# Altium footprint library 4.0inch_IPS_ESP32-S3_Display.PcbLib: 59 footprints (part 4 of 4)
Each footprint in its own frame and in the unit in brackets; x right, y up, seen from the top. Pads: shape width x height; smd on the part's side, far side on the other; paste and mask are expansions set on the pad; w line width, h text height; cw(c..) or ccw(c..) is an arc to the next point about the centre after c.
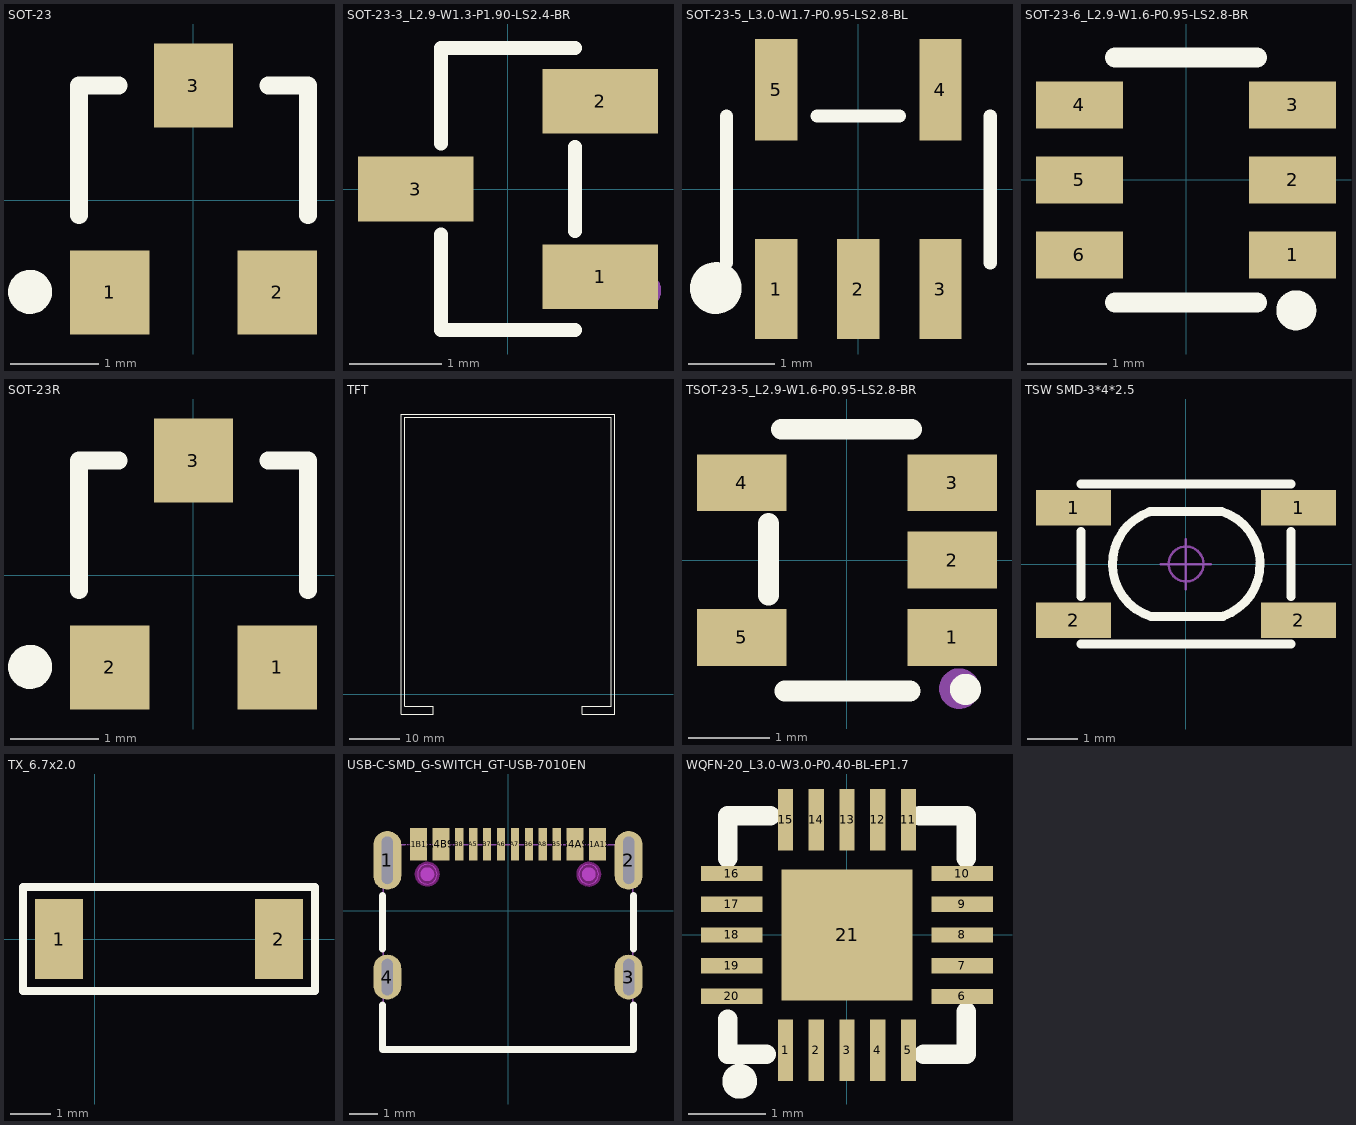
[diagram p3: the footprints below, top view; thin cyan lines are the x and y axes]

## SOT-23 [mm]
pads (3):
  rect 0.9x0.95 smd: 1(-0.95,-1.048) 2(0.95,-1.048) 3(0,1.302)
Top Overlay:
  circle w0.25: c-1.856,-1.041 r0.125
  lines w0.2: -1.3,-0.173 -1.3,1.302 -0.85,1.302 ; 0.85,1.302 1.3,1.302 1.3,-0.173
3D body "SOT-23-3.STEP": height 1.2, standoff 0, extent -1.448,-1.327 1.452,1.473

## SOT-23-3_L2.9-W1.3-P1.90-LS2.4-BR [mm]
pads (3):
  rect 1.25x0.7 smd: 1(1,-0.95) 2(1,0.95) 3(-1,0)
Top Overlay:
  lines w0.152: -0.726,-0.495 -0.726,-1.526 0.726,-1.526 ; -0.726,0.495 -0.726,1.526 0.726,1.526 ; 0.726,-0.455 0.726,0.455
Mechanical 15:
  circle w0.2: c1.46,-1.1 r0.1
3D body "bss138.stp": height 1.1, standoff 0, extent -1.1,-1.491 1.3,1.409

## SOT-23-5_L3.0-W1.7-P0.95-LS2.8-BL [mm]
pads (5):
  rect 0.49x1.157 smd: 1(-0.95,-1.154) 2(0,-1.154) 3(0.95,-1.154)
  rect 0.49x1.175 smd: 4(0.95,1.154) 5(-0.95,1.154)
Top Overlay:
  circle w0.3: c-1.651,-1.143 r0.15
  lines w0.152: -1.526,-0.851 -1.526,0.851 ; -0.476,0.851 0.476,0.851 ; 1.526,-0.851 1.526,0.851
3D body "CircuitWorks-SOT-23-5.STEP": height 1.1, standoff 0, extent -1.476,-1.366 1.524,1.134

## SOT-23-6_L2.9-W1.6-P0.95-LS2.8-BR [mm]
pads (6):
  rect 1.1x0.6 smd paste+0 mask+0.051: 1(1.35,-0.95) 2(1.35,0) 3(1.35,0.95) 4(-1.35,0.95) 5(-1.35,0) 6(-1.35,-0.95)
Top Overlay:
  circle w0.254: c1.397,-1.651 r0.127
  lines w0.254: -0.9,-1.55 0.9,-1.55 ; -0.9,1.55 0.9,1.55
Mechanical 6:
  circle w0.2: c1.4,-0.95 r0.1

## SOT-23R [mm]
pads (3):
  rect 0.9x0.95 smd: 1(0.95,-1.048) 2(-0.95,-1.048) 3(0,1.302)
Top Overlay:
  circle w0.25: c-1.856,-1.041 r0.125
  lines w0.2: -1.3,-0.173 -1.3,1.302 -0.85,1.302 ; 0.85,1.302 1.3,1.302 1.3,-0.173
3D body "1364886p.stp": height 1, standoff 0, extent -1.45,-0.998 1.45,1.302

## TFT [mm]
Top Overlay:
  lines w0.1: 133.223,-3.937 133.223,56.063 175.823,56.063 175.823,-3.937 169.418,-3.937 169.418,-2.413 175.133,-2.413 175.133,55.372 133.858,55.372 133.858,-2.413 139.558,-2.413 139.558,-3.937 133.223,-3.937
3D body: height 0.1, standoff 0, extent 133.153,-2.413 175.753,55.315
3D body: height 2.3, standoff 0.1, extent 133.223,-3.937 175.823,56.063
3D body: height 3.3, standoff 2.3, extent 133.731,-2.286 175.133,55.63

## TSOT-23-5_L2.9-W1.6-P0.95-LS2.8-BR [mm]
pads (5):
  rect 1.1x0.7 smd: 1(1.294,-0.951) 2(1.294,-0.001) 3(1.294,0.951) 4(-1.294,0.951) 5(-1.294,-0.949)
Top Overlay:
  circle w0.254: c1.456,-1.589 r0.064
  lines w0.254: -0.966,-0.433 -0.966,0.451 ; -0.806,1.609 0.794,1.609 ; -0.766,-1.609 0.774,-1.609
Mechanical 6:
  circle w0.25: c1.38,-1.58 r0.125
3D body "User Library-TSSOP-5 (SOT-23-5 PITCH 0_65).STEP": height 1.15, standoff 0.04, extent -1.252,-1.125 0.998,1.125

## TSW SMD-3*4*2.5 [mm] "3*4*2.5mm"
height 2.5
pads (4):
  rect 1.5x0.7 smd: 1(-2.25,1.125) 1(2.25,1.125) 2(-2.25,-1.125) 2(2.25,-1.125)
Top Overlay:
  lines w0.178: -2.1,-1.6 2.1,-1.6 ; -2.1,-0.65 -2.1,0.65 ; -2.1,1.6 2.1,1.6 ; -0.738,1.037 ccw(c-0.372,0) -0.7,-1.05 0.737,-1.05 ; -0.725,1.05 0.712,1.05 cw(c0.384,0) 0.75,-1.037 ; 2.1,-0.65 2.1,0.65
Mechanical 15:
  circle w0.05: c0,0 r0.35
  lines w0.05: -0.5,0 0.5,0 ; 0,-0.5 0,0.5
3D body "key.STEP": height 2.5, standoff 0, extent -2.6,-1.65 2.6,1.6

## TX_6.7x2.0 [mm]
pads (2):
  rect 1.2x2 smd: 1(-0.889,0) 2(4.611,0)
Top Overlay:
  lines w0.2: -1.789,-1.3 5.511,-1.3 5.511,1.3 -1.789,1.3 -1.789,-1.3

## USB-C-SMD_G-SWITCH_GT-USB-7010EN [mm]
pads (16):
  oval 1x2.1 hole 0.4 slot 1.7 at 90 deg mask+0.05: 1(-4.32,1.802) 2(4.32,1.802)
  oval 1x1.6 hole 0.4 slot 1.3 at 90 deg mask+0.05: 3(4.32,-2.378) 4(-4.32,-2.378)
  rect 0.6x1.15 smd mask+0.05: A1B12(-3.2,2.378) A4B9(-2.4,2.378) B1A12(3.2,2.378) B4A9(2.4,2.378)
  rect 0.3x1.15 smd mask+0.05: A5(-1.25,2.378) A6(-0.25,2.378) A7(0.25,2.378) A8(1.25,2.378) B5(1.75,2.378) B6(0.75,2.378) B7(-0.75,2.378) B8(-1.75,2.378)
Top Overlay:
  lines w0.254: -4.5,-3.386 -4.5,-4.978 4.5,-4.978 4.5,-3.386 ; -4.5,-1.369 -4.5,0.544 ; 4.5,-1.369 4.5,0.544
Top Paste:
  region: 3.82,2.352 3.82,2.452 3.896,2.636 4.037,2.776 4.221,2.852 4.42,2.852 4.603,2.776 4.744,2.636 4.82,2.452 4.82,2.352 4.82,1.252 4.82,1.153 4.744,0.969 4.603,0.829 4.42,0.752 4.221,0.752 4.037,0.829 3.896,0.969 3.82,1.153 3.82,1.252
  region: 3.82,-2.078 3.82,-1.978 3.896,-1.794 4.037,-1.654 4.221,-1.578 4.42,-1.578 4.603,-1.654 4.744,-1.794 4.82,-1.978 4.82,-2.078 4.82,-2.678 4.82,-2.777 4.744,-2.961 4.603,-3.101 4.42,-3.178 4.221,-3.178 4.037,-3.101 3.896,-2.961 3.82,-2.777 3.82,-2.678
  region: -4.82,-2.078 -4.82,-1.978 -4.744,-1.794 -4.603,-1.654 -4.419,-1.578 -4.221,-1.578 -4.037,-1.654 -3.896,-1.794 -3.82,-1.978 -3.82,-2.078 -3.82,-2.678 -3.82,-2.777 -3.896,-2.961 -4.037,-3.101 -4.221,-3.178 -4.419,-3.178 -4.603,-3.101 -4.744,-2.961 -4.82,-2.777 -4.82,-2.678
  region: -4.82,2.352 -4.82,2.452 -4.744,2.636 -4.603,2.776 -4.419,2.852 -4.221,2.852 -4.037,2.776 -3.896,2.636 -3.82,2.452 -3.82,2.352 -3.82,1.252 -3.82,1.153 -3.896,0.969 -4.037,0.829 -4.221,0.752 -4.419,0.752 -4.603,0.829 -4.744,0.969 -4.82,1.153 -4.82,1.252
  region: -3.5,2.952 -2.9,2.952 -2.9,1.802 -3.5,1.802
  region: -2.7,2.952 -2.1,2.952 -2.1,1.802 -2.7,1.802
  region: -1.9,2.952 -1.6,2.952 -1.6,1.802 -1.9,1.802
  region: -1.4,2.952 -1.1,2.952 -1.1,1.802 -1.4,1.802
  region: -0.9,2.952 -0.6,2.952 -0.6,1.802 -0.9,1.802
  region: -0.4,2.952 -0.1,2.952 -0.1,1.802 -0.4,1.802
  region: 0.1,2.952 0.4,2.952 0.4,1.802 0.1,1.802
  region: 0.6,2.952 0.9,2.952 0.9,1.802 0.6,1.802
  region: 1.1,2.952 1.4,2.952 1.4,1.802 1.1,1.802
  region: 1.6,2.952 1.9,2.952 1.9,1.802 1.6,1.802
  region: 2.1,2.952 2.7,2.952 2.7,1.802 2.1,1.802
  region: 2.9,2.952 3.5,2.952 3.5,1.802 2.9,1.802
Keep-Out Layer:
  board cut-out: -2.54,1.302 -2.54,1.372 -2.593,1.501 -2.692,1.599 -2.82,1.652 -2.96,1.652 -3.088,1.599 -3.187,1.501 -3.24,1.372 -3.24,1.302 -3.24,1.233 -3.187,1.104 -3.088,1.006 -2.96,0.952 -2.82,0.952 -2.692,1.006 -2.593,1.104 -2.54,1.233
  board cut-out: 3.24,1.302 3.24,1.372 3.187,1.5 3.088,1.599 2.96,1.652 2.82,1.652 2.692,1.599 2.593,1.5 2.54,1.372 2.54,1.302 2.54,1.232 2.593,1.104 2.692,1.005 2.82,0.952 2.96,0.952 3.088,1.005 3.187,1.104 3.24,1.232
Keep-Out Layer:
  circle w0.1: c2.893,1.305 r0.4
  circle w0.1: c-2.89,1.307 r0.4
Mechanical 1:
  circle w0.005: c-2.89,1.302 r0.35
  circle w0.005: c2.89,1.302 r0.35
Mechanical 6:
  circle w0.25: c2.89,1.302 r0.125
  circle w0.25: c-2.89,1.302 r0.125
Mechanical 15:
  region: -4.41,2.597 -4.41,2.622 -4.445,2.657 -4.495,2.657 -4.53,2.622 -4.53,2.597 -4.53,2.572 -4.495,2.537 -4.445,2.537 -4.41,2.572
  region: 4.17,-1.978 4.47,-1.978 4.47,-2.778 4.17,-2.778
  region: -4.47,-1.978 -4.17,-1.978 -4.17,-2.778 -4.47,-2.778
  region: -4.47,2.352 -4.17,2.352 -4.17,1.252 -4.47,1.252
  region: 4.17,2.352 4.47,2.352 4.47,1.252 4.17,1.252
  region: 1.65,2.597 1.85,2.597 1.85,1.847 1.65,1.847
  region: 1.15,2.597 1.35,2.597 1.35,1.847 1.15,1.847
  region: 0.65,2.597 0.85,2.597 0.85,1.847 0.65,1.847
  region: 0.15,2.597 0.35,2.597 0.35,1.847 0.15,1.847
  region: -0.35,2.597 -0.15,2.597 -0.15,1.847 -0.35,1.847
  region: -0.85,2.597 -0.65,2.597 -0.65,1.847 -0.85,1.847
  region: -1.35,2.597 -1.15,2.597 -1.15,1.847 -1.35,1.847
  region: -1.85,2.597 -1.65,2.597 -1.65,1.847 -1.85,1.847
  region: 3,2.597 3.4,2.597 3.4,1.847 3,1.847
  region: 2.2,2.597 2.6,2.597 2.6,1.847 2.2,1.847
  region: -2.6,2.597 -2.2,2.597 -2.2,1.847 -2.6,1.847
  region: -3.4,2.597 -3,2.597 -3,1.847 -3.4,1.847
  lines w0.051: -4.47,-4.983 4.47,-4.983 4.47,2.367 -4.47,2.367 -4.47,-4.983
3D body "User Library-USB Type C Port (SMD Type).STEP": height 1.61, standoff -2.6, extent -4.505,-5.028 4.435,2.872

## WQFN-20_L3.0-W3.0-P0.40-BL-EP1.7 [mm]
pads (21):
  rect 0.2x0.8 smd paste-100 mask+0.051: 1(-0.8,-1.5) 2(-0.4,-1.5) 3(0,-1.5) 4(0.4,-1.5) 5(0.8,-1.5) 11(0.8,1.5) 12(0.4,1.5) 13(0,1.5) 14(-0.4,1.5) 15(-0.8,1.5)
  rect 0.8x0.2 smd paste-100 mask+0.051: 6(1.5,-0.8) 7(1.5,-0.4) 8(1.5,0) 9(1.5,0.4) 10(1.5,0.8) 16(-1.5,0.8) 17(-1.5,0.4) 18(-1.5,0) 19(-1.5,-0.4) 20(-1.5,-0.8)
  rect 1.7x1.7 smd paste-100 mask+0.051: 21(0,0)
Top Overlay:
  circle w0.254: c-1.397,-1.905 r0.1
  lines w0.254: -1.55,-1.1 -1.55,-1.55 -1.05,-1.55 ; -1.55,1 -1.55,1.55 -1,1.55 ; 0.95,1.55 1.55,1.55 1.55,1 ; 1,-1.55 1.55,-1.55 1.55,-1
Top Paste:
  region: 0.68,0.68 0.68,-0.68 -0.68,-0.68 -0.68,0.68
  region: -1.1,0.7 -1.1,0.9 -1.9,0.9 -1.9,0.7
  region: -1.1,0.3 -1.1,0.5 -1.9,0.5 -1.9,0.3
  region: -1.1,-0.1 -1.1,0.1 -1.9,0.1 -1.9,-0.1
  region: -1.1,-0.5 -1.1,-0.3 -1.9,-0.3 -1.9,-0.5
  region: -1.1,-0.9 -1.1,-0.7 -1.9,-0.7 -1.9,-0.9
  region: 1.9,0.7 1.9,0.9 1.1,0.9 1.1,0.7
  region: 1.9,0.3 1.9,0.5 1.1,0.5 1.1,0.3
  region: 1.9,-0.1 1.9,0.1 1.1,0.1 1.1,-0.1
  region: 1.9,-0.5 1.9,-0.3 1.1,-0.3 1.1,-0.5
  region: 1.9,-0.9 1.9,-0.7 1.1,-0.7 1.1,-0.9
  region: -0.7,-1.1 -0.9,-1.1 -0.9,-1.9 -0.7,-1.9
  region: -0.3,-1.1 -0.5,-1.1 -0.5,-1.9 -0.3,-1.9
  region: 0.1,-1.1 -0.1,-1.1 -0.1,-1.9 0.1,-1.9
  region: 0.5,-1.1 0.3,-1.1 0.3,-1.9 0.5,-1.9
  region: 0.9,-1.1 0.7,-1.1 0.7,-1.9 0.9,-1.9
  region: -0.7,1.9 -0.9,1.9 -0.9,1.1 -0.7,1.1
  region: -0.3,1.9 -0.5,1.9 -0.5,1.1 -0.3,1.1
  region: 0.1,1.9 -0.1,1.9 -0.1,1.1 0.1,1.1
  region: 0.5,1.9 0.3,1.9 0.3,1.1 0.5,1.1
  region: 0.9,1.9 0.7,1.9 0.7,1.1 0.9,1.1
3D body "User Library-WQFN-20.STEP": height 0.8, standoff 0, extent -1.51,-1.51 1.51,1.51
